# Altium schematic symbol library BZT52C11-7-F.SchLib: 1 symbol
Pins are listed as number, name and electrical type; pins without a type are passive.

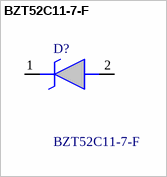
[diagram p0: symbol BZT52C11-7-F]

## BZT52C11-7-F
designator D?
Diodes Inc BZT52C11-7-F Zener Diode, 11V 5% 500 mW SMT 2-Pin SOD-123; Manufacturer_Name: Diodes Incorporated; Geometry.Height: 1.45mm
footprint SOD3716X145N
pins: 1 K, 2 A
